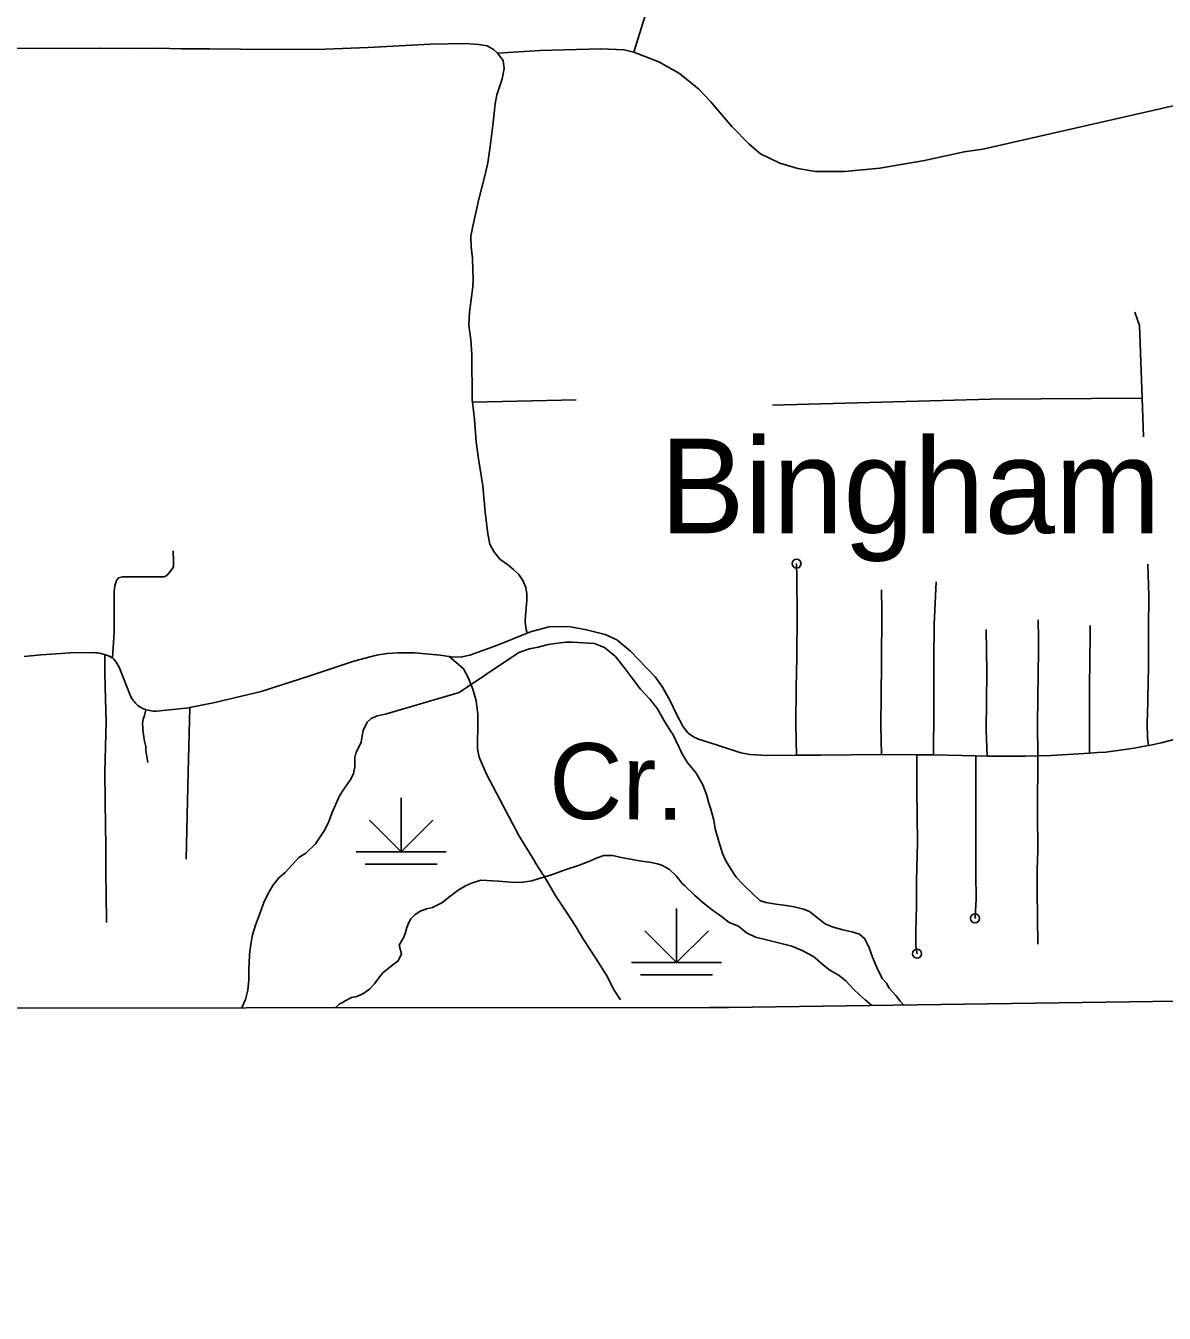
# Model space of a CAD drawing. Extents: x -19 to 366, y -4 to 359.
# Drawn here: x 154.399 to 155.599, y 179.654 to 181.01 of the extents above; entities that cross this region are included whole.
import ezdxf

# ---------------------------------------------------------------- set-up
doc = ezdxf.new("R2010")
doc.units = 0
for name, color, linetype in [('Level 2', 7, 'Continuous'), ('Level 24', 7, 'Continuous'), ('Level 31', 7, 'Continuous'), ('Level 35', 7, 'Continuous'), ('Level 44', 7, 'Continuous'), ('Level 47', 7, 'Continuous'), ('Level 60', 7, 'Continuous')]:
    doc.layers.add(name, color=color, linetype=linetype)

msp = doc.modelspace()

# ---------------------------------------------------------------- linework, layer by layer
at = {"layer": 'Level 2'}
msp.add_lwpolyline([(152.3808, 179.9473), (153.0932, 179.9566), (153.1262, 179.957), (154.119, 179.9749), (154.1433, 179.9749), (155.1201, 179.9757), (155.1401, 179.9758), (155.7117, 179.984)], dxfattribs=at)
at = {"layer": 'Level 31'}
for points in [[(155.0402, 180.9827), (155.0511, 181.0176), (155.0626, 181.0526), (155.0745, 181.0874), (155.0994, 181.148)], [(154.3706, 180.9852), (154.3895, 180.9865), (154.4783, 180.9868), (154.5131, 180.9865), (154.5386, 180.9869), (154.5634, 180.9862), (154.5931, 180.9862), (154.6256, 180.9856), (154.6745, 180.9852), (154.7151, 180.9856), (154.7604, 180.9876), (154.8258, 180.9911), (154.863, 180.9917), (154.8769, 180.9907), (154.8858, 180.9893), (154.8925, 180.9854), (154.8965, 180.9815)], [(154.8965, 180.9815), (154.9417, 180.9842), (155.0056, 180.9861), (155.0299, 180.9851), (155.0402, 180.9827)], [(154.8965, 180.9815), (154.9027, 180.9737), (154.9037, 180.9653), (154.9016, 180.9545), (154.8958, 180.9377), (154.894, 180.9281), (154.8919, 180.9084), (154.889, 180.8832), (154.8864, 180.8659), (154.8838, 180.8552), (154.8769, 180.8276), (154.8705, 180.7992), (154.8686, 180.7887), (154.8687, 180.7774), (154.8701, 180.7656), (154.8707, 180.7524), (154.8708, 180.7433), (154.8705, 180.7352), (154.867, 180.7084), (154.8662, 180.6949), (154.8685, 180.6794), (154.8696, 180.6641), (154.8698, 180.616), (154.8701, 180.6137)], [(155.0402, 180.9827), (155.0665, 180.9725), (155.0885, 180.9599), (155.1088, 180.9437), (155.1211, 180.9304), (155.1435, 180.9041), (155.1617, 180.8857), (155.1739, 180.8755), (155.194, 180.8655), (155.2132, 180.8599), (155.2318, 180.8569), (155.2622, 180.8569), (155.2996, 180.8602), (155.3466, 180.8683), (155.3882, 180.8775), (155.4079, 180.8802), (155.6164, 180.9277)], [(155.5682, 180.7085), (155.573, 180.6944), (155.5758, 180.6179)], [(154.8701, 180.6137), (154.9796, 180.6161)], [(154.8701, 180.6137), (154.8722, 180.5956), (154.8741, 180.572), (154.8764, 180.554), (154.8811, 180.5255), (154.8837, 180.4979), (154.8864, 180.4748), (154.8884, 180.464), (154.8926, 180.4563), (154.8992, 180.4484), (154.9072, 180.4426), (154.9136, 180.4373), (154.9191, 180.4322), (154.9232, 180.4258), (154.9263, 180.4184), (154.9275, 180.4118), (154.9276, 180.4046), (154.9261, 180.389), (154.9259, 180.3818), (154.9268, 180.3742), (154.9278, 180.3701)], [(155.5758, 180.6179), (155.4162, 180.617), (155.1864, 180.6104)], [(155.5758, 180.6179), (155.5772, 180.5772)], [(154.5549, 180.4569), (154.555, 180.446), (154.5551, 180.4402), (154.5518, 180.4357), (154.548, 180.4309), (154.5453, 180.4295), (154.5127, 180.4296), (154.5013, 180.4297), (154.4972, 180.4285), (154.495, 180.4258), (154.4933, 180.4203), (154.4925, 180.4141), (154.4926, 180.3946), (154.4927, 180.3713), (154.4909, 180.3441)], [(155.2117, 180.4436), (155.2117, 180.4415), (155.2119, 180.4306), (155.2125, 180.3891), (155.212, 180.3445), (155.2114, 180.3131), (155.2111, 180.2736), (155.2116, 180.2416)], [(155.5819, 180.4429), (155.583, 180.4093), (155.5826, 180.3755), (155.5826, 180.3514), (155.5827, 180.3319), (155.5824, 180.3216), (155.5818, 180.298), (155.5814, 180.2754), (155.5817, 180.2598), (155.5825, 180.2519)], [(155.3013, 180.4161), (155.3016, 180.3936), (155.3013, 180.3378), (155.3006, 180.2727), (155.3014, 180.2423)], [(155.359, 180.4244), (155.3568, 180.3798), (155.3563, 180.3414), (155.3565, 180.2908), (155.356, 180.242)], [(155.2116, 180.2416), (155.1811, 180.2415), (155.1625, 180.2424), (155.1529, 180.2442), (155.1273, 180.2526), (155.1084, 180.2585), (155.1031, 180.2611), (155.0974, 180.2649), (155.0921, 180.2716), (155.0848, 180.2856), (155.0784, 180.2988), (155.0704, 180.3133), (155.0629, 180.3242), (155.0369, 180.3513), (155.0223, 180.3632), (155.01, 180.3687), (154.9902, 180.3736), (154.9734, 180.3769), (154.9617, 180.3773), (154.9509, 180.3768), (154.9324, 180.372), (154.9278, 180.3701)], [(155.4665, 180.3842), (155.4666, 180.3643), (155.4666, 180.3523), (155.4658, 180.2754), (155.4659, 180.2409)], [(155.5213, 180.3784), (155.5213, 180.3713), (155.5208, 180.3391), (155.5203, 180.316), (155.5205, 180.2953), (155.5206, 180.2657), (155.5205, 180.2438)], [(154.9278, 180.3701), (154.8965, 180.3575), (154.8674, 180.347), (154.859, 180.3453), (154.8501, 180.3451), (154.8456, 180.3457)], [(155.4116, 180.3743), (155.4122, 180.33), (155.4117, 180.2676), (155.4127, 180.2406)], [(154.4826, 180.3477), (154.4807, 180.3483), (154.4788, 180.3488), (154.4769, 180.3492), (154.4749, 180.3495), (154.473, 180.3497), (154.471, 180.3498), (154.4465, 180.3497), (154.4156, 180.3475), (154.3977, 180.3457)], [(154.8456, 180.3457), (154.836, 180.347), (154.8092, 180.3496), (154.7915, 180.3494), (154.7802, 180.349), (154.7689, 180.347), (154.745, 180.3407), (154.6987, 180.3253), (154.6474, 180.3089), (154.5988, 180.2973), (154.5723, 180.2918)], [(154.4826, 180.3477), (154.4826, 180.3285), (154.4835, 180.3006), (154.484, 180.2775), (154.4828, 180.2236), (154.483, 180.1931), (154.4835, 180.1673), (154.4838, 180.1466), (154.4838, 180.1165), (154.4841, 180.0961), (154.4846, 180.0652)], [(154.4909, 180.3441), (154.4906, 180.3443), (154.4886, 180.3453), (154.4867, 180.3462), (154.4846, 180.347), (154.4826, 180.3477)], [(154.526, 180.2896), (154.5249, 180.29), (154.5233, 180.2906), (154.5217, 180.2914), (154.5201, 180.2922), (154.5187, 180.2932), (154.5174, 180.2942), (154.5161, 180.2953), (154.515, 180.2965), (154.5139, 180.2978), (154.5128, 180.2991), (154.5119, 180.3005), (154.511, 180.3019), (154.5102, 180.3034), (154.5096, 180.305), (154.4978, 180.3343), (154.4969, 180.3362), (154.4959, 180.338), (154.4947, 180.3397), (154.4934, 180.3413), (154.4921, 180.3429), (154.4909, 180.3441)], [(154.8456, 180.3457), (154.8525, 180.3397), (154.8607, 180.3327), (154.8656, 180.3235), (154.8705, 180.3114), (154.8742, 180.2988), (154.8757, 180.2848), (154.8759, 180.2704), (154.8755, 180.2559), (154.8756, 180.2484), (154.8772, 180.2396), (154.885, 180.2217), (154.919, 180.1571), (154.9358, 180.1298), (154.9362, 180.1287), (154.9409, 180.1216), (154.9415, 180.1205), (154.9442, 180.116), (154.9449, 180.1151), (154.9495, 180.1074), (154.9582, 180.0931), (154.9692, 180.0762), (154.9792, 180.0613), (154.9872, 180.0474), (155, 180.0282), (155.0113, 180.0098), (155.0197, 179.994), (155.0262, 179.9837)], [(154.528, 180.2339), (154.526, 180.2467), (154.5259, 180.251), (154.5244, 180.2566), (154.5231, 180.2655), (154.5224, 180.2752), (154.5232, 180.2796), (154.5244, 180.2835), (154.526, 180.2896)], [(154.5723, 180.2918), (154.5717, 180.2916), (154.551, 180.2893), (154.5372, 180.2882), (154.5354, 180.2882), (154.5336, 180.2882), (154.5319, 180.2884), (154.5301, 180.2886), (154.5284, 180.289), (154.5266, 180.2894), (154.526, 180.2896)], [(154.5723, 180.2918), (154.5707, 180.2239), (154.5684, 180.1322)], [(155.6424, 180.2675), (155.6332, 180.2647), (155.624, 180.262), (155.6147, 180.2595), (155.6054, 180.2571), (155.596, 180.2548), (155.5866, 180.2527), (155.5825, 180.2519)], [(155.3014, 180.2423), (155.2373, 180.2416), (155.2116, 180.2416)], [(155.3385, 180.2421), (155.3014, 180.2423)], [(155.3385, 180.2421), (155.3386, 180.2055), (155.3391, 180.1496), (155.3383, 180.1091), (155.3382, 180.0825), (155.3373, 180.0564), (155.3375, 180.0401), (155.3388, 180.0325)], [(155.356, 180.242), (155.3385, 180.2421)], [(155.4005, 180.2409), (155.356, 180.242)], [(155.3998, 180.0697), (155.4002, 180.0779), (155.4009, 180.09), (155.4006, 180.1166), (155.4006, 180.1772), (155.4005, 180.2409)], [(155.4127, 180.2406), (155.4005, 180.2409)], [(155.4659, 180.2409), (155.4526, 180.2406), (155.4393, 180.2405), (155.426, 180.2405), (155.4127, 180.2406)], [(155.4659, 180.2409), (155.4656, 180.1811), (155.4659, 180.1412), (155.4652, 180.1209), (155.4652, 180.0986), (155.4659, 180.0426)], [(155.5205, 180.2438), (155.4799, 180.2414), (155.4659, 180.2409)], [(155.5825, 180.2519), (155.575, 180.2505), (155.5676, 180.2492), (155.5602, 180.248), (155.5527, 180.2468), (155.5452, 180.2458), (155.5377, 180.2449), (155.5291, 180.2444), (155.5205, 180.2438)]]:
    msp.add_lwpolyline(points, dxfattribs=at)
for centre in [(155.2117, 180.4436), (155.3998, 180.0697), (155.3388, 180.0325)]:
    msp.add_circle(centre, 0.00473, dxfattribs=at)
at = {"layer": 'Level 35'}
msp.add_lwpolyline([(154.7254, 179.9754), (154.7297, 179.9792), (154.7333, 179.981), (154.7368, 179.9832), (154.7426, 179.9864), (154.7483, 179.9873), (154.7548, 179.9902), (154.7617, 179.9951), (154.7668, 180.0008), (154.7716, 180.0072), (154.7758, 180.0124), (154.7847, 180.0197), (154.7919, 180.0249), (154.7953, 180.0322), (154.7931, 180.0414), (154.7978, 180.0499), (154.7996, 180.0549), (154.8009, 180.0601), (154.8031, 180.0655), (154.8054, 180.0691), (154.8095, 180.0734), (154.815, 180.0772), (154.8216, 180.0797), (154.8282, 180.0812), (154.8379, 180.0862), (154.8464, 180.0929), (154.8551, 180.0993), (154.8628, 180.1039), (154.8693, 180.1067), (154.8789, 180.1098), (154.8791, 180.1098), (154.8977, 180.109), (154.9064, 180.1081), (154.9146, 180.1074), (154.9238, 180.1077), (154.9329, 180.1093), (154.9406, 180.1118), (154.9535, 180.1156), (154.968, 180.1209), (154.9819, 180.1255), (154.9929, 180.1298), (155.0017, 180.1335), (155.0088, 180.1358), (155.0181, 180.1358), (155.0269, 180.134), (155.0402, 180.1315), (155.0484, 180.1299), (155.0568, 180.1291), (155.0653, 180.1271), (155.0705, 180.1254), (155.0778, 180.1212), (155.0848, 180.1147), (155.0917, 180.1062), (155.0935, 180.1042), (155.1043, 180.0942), (155.1125, 180.0868), (155.1216, 180.0793), (155.1326, 180.0718), (155.1408, 180.0654), (155.1504, 180.0615), (155.1589, 180.0543), (155.1685, 180.0499), (155.1816, 180.0466), (155.194, 180.0435), (155.2068, 180.0403), (155.2177, 180.0359), (155.2297, 180.0295), (155.2401, 180.0205), (155.2467, 180.015), (155.2567, 180.0096), (155.2639, 180.0037), (155.2715, 179.9954), (155.2782, 179.9891), (155.284, 179.9838), (155.2909, 179.9779)], dxfattribs=at)
at = {"layer": 'Level 44'}
for p, q in [((154.7951, 180.1966), (154.7951, 180.1398)), ((154.7951, 180.1398), (154.7616, 180.1732)), ((154.7951, 180.1398), (154.8286, 180.1732)), ((154.7477, 180.1398), (154.8424, 180.1398)), ((154.7572, 180.1268), (154.833, 180.1268)), ((155.0853, 180.08), (155.0853, 180.0232)), ((155.0853, 180.0232), (155.0518, 180.0567)), ((155.0853, 180.0232), (155.1188, 180.0567)), ((155.0379, 180.0232), (155.1326, 180.0232)), ((155.0474, 180.0103), (155.1232, 180.0103))]:
    msp.add_line(p, q, dxfattribs=at)
at = {"layer": 'Level 47'}
for points in [[(154.627, 179.9753), (154.6309, 179.9842), (154.6335, 179.9939), (154.6345, 180.005), (154.6344, 180.017), (154.6348, 180.0221), (154.6353, 180.0316), (154.6367, 180.0425), (154.6383, 180.0522), (154.6414, 180.0626), (154.6456, 180.0739), (154.6502, 180.0864), (154.6549, 180.0958), (154.6599, 180.1045), (154.6663, 180.1125), (154.6728, 180.1182), (154.6873, 180.134), (154.6946, 180.1384), (154.7049, 180.1484), (154.714, 180.1619), (154.7184, 180.1708), (154.7221, 180.1806), (154.73, 180.1989), (154.7345, 180.206), (154.742, 180.2165), (154.7448, 180.2225), (154.7461, 180.2294), (154.7463, 180.2391), (154.7478, 180.2448), (154.7512, 180.2514), (154.753, 180.2554), (154.7538, 180.2619), (154.7549, 180.2678), (154.7592, 180.2765), (154.7633, 180.2802), (154.7702, 180.2833), (154.7796, 180.2852), (154.8562, 180.3076), (154.883, 180.3258), (154.9191, 180.35), (154.9303, 180.3536), (154.9396, 180.3556), (154.9501, 180.3583), (154.9603, 180.3596), (154.9686, 180.3608), (154.9754, 180.3609), (154.9987, 180.3595), (155.0093, 180.3551), (155.0205, 180.3461), (155.0299, 180.3342), (155.0386, 180.3228), (155.0474, 180.3113), (155.0572, 180.3008), (155.0653, 180.2905), (155.0717, 180.2786), (155.0792, 180.2668)], [(155.0792, 180.2668), (155.0812, 180.2638), (155.0912, 180.243), (155.0966, 180.2344), (155.106, 180.2227), (155.113, 180.2106), (155.1167, 180.2004), (155.1194, 180.191), (155.1209, 180.1859), (155.1245, 180.1731), (155.1259, 180.1642), (155.1298, 180.1508), (155.1336, 180.1382), (155.1368, 180.131), (155.1422, 180.1223), (155.1481, 180.1131), (155.1552, 180.1057), (155.1577, 180.1033), (155.1731, 180.0887), (155.1792, 180.0866), (155.1899, 180.0845), (155.2009, 180.0831), (155.2092, 180.082), (155.219, 180.0794), (155.2255, 180.0771), (155.2325, 180.0712), (155.2418, 180.0639), (155.2492, 180.0607), (155.2605, 180.0576), (155.27, 180.0556), (155.2782, 180.053), (155.2837, 180.048), (155.2883, 180.0386), (155.2916, 180.0288), (155.2963, 180.0181), (155.3019, 180.0065), (155.3064, 180.0015), (155.3094, 179.9961), (155.3164, 179.9883), (155.3208, 179.9824), (155.3248, 179.9784)]]:
    msp.add_lwpolyline(points, dxfattribs=at)
at = {"layer": 'Level 60'}
for points in [[(0, 180.8999), (7.1228, 180.9044), (14.2457, 180.9176), (21.3685, 180.9397), (28.4912, 180.9706), (35.614, 181.0103), (42.7366, 181.0589), (49.8592, 181.1163), (56.9818, 181.1825), (64.1042, 181.2575), (71.2266, 181.3414), (78.3488, 181.4341), (85.4709, 181.5357), (92.5929, 181.646), (99.7147, 181.7652), (106.8364, 181.8933), (113.9579, 182.0301), (121.0793, 182.1758), (128.2005, 182.3303), (135.3214, 182.4936), (142.4422, 182.6658), (149.5627, 182.8468), (156.683, 183.0366), (163.8031, 183.2352), (170.9229, 183.4427), (178.0425, 183.659), (185.1617, 183.8841), (192.2807, 184.1181), (199.3994, 184.3608), (206.5178, 184.6124), (213.6359, 184.8728), (220.7537, 185.1421), (227.8711, 185.4201), (234.9881, 185.707), (242.1048, 186.0027), (249.2212, 186.3073), (256.3371, 186.6206), (263.4526, 186.9428), (270.5678, 187.2738), (277.6825, 187.6136), (284.7968, 187.9622), (291.9107, 188.3197), (299.0241, 188.6859), (306.1371, 189.061), (313.2495, 189.4449), (320.3615, 189.8377), (327.4731, 190.2392), (334.5841, 190.6495), (341.6946, 191.0687)], [(0, 172.2839), (7.1335, 172.2883), (14.267, 172.3015), (21.4005, 172.3236), (28.5339, 172.3544), (35.6673, 172.3941), (42.8006, 172.4426), (49.9339, 172.4999), (57.0671, 172.566), (64.2002, 172.6409), (71.3332, 172.7246), (78.4661, 172.8172), (85.5989, 172.9186), (92.7315, 173.0287), (99.8641, 173.1477), (106.9964, 173.2755), (114.1286, 173.4122), (121.2606, 173.5576), (128.3925, 173.7119), (135.5241, 173.8749), (142.6555, 174.0468), (149.7867, 174.2275), (156.9177, 174.417), (164.0485, 174.6153), (171.179, 174.8224), (178.3092, 175.0383), (185.4392, 175.2631), (192.5688, 175.4966), (199.6982, 175.739), (206.8273, 175.9902), (213.9561, 176.2502), (221.0845, 176.5189), (228.2126, 176.7965), (235.3404, 177.083), (242.4677, 177.3782), (249.5948, 177.6822), (256.7214, 177.995), (263.8476, 178.3167), (270.9735, 178.6471), (278.0989, 178.9863), (285.2239, 179.3344), (292.3485, 179.6912), (299.4726, 180.0569), (306.5963, 180.4314), (313.7195, 180.8146), (320.8422, 181.2067), (327.9644, 181.6076), (335.0862, 182.0172), (342.2074, 182.4357)]]:
    msp.add_spline(points, degree=3, dxfattribs=at)

# ---------------------------------------------------------------- texts
at = {"layer": 'Level 24'}
msp.add_text('Bingham', height=0.1, dxfattribs=at).set_placement((155.0678, 180.4754))
at = {"layer": 'Level 35'}
msp.add_text('Cr.', height=0.08, rotation=359.5008, dxfattribs=at).set_placement((154.9507, 180.1747))

doc.saveas('drawing.dxf')
